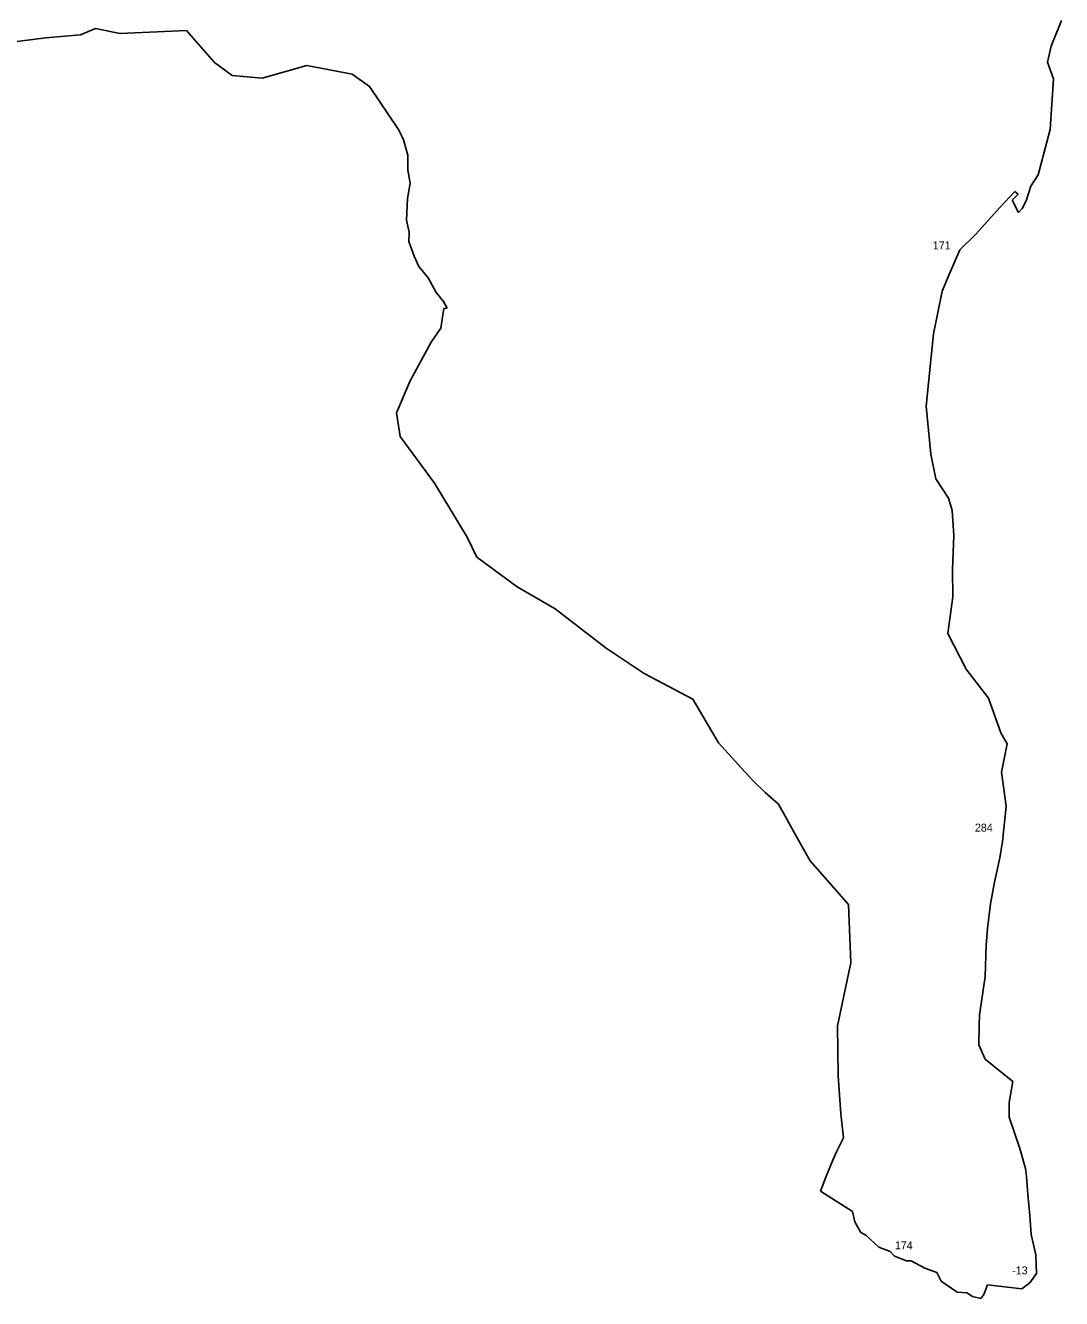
# Model space of a CAD drawing. Extents: x -787692 to -782531, y -972586 to -966265.
# Drawn here: x -783835 to -782540, y -972494 to -970904 of the extents above; entities that cross this region are included whole.
import ezdxf

# ---------------------------------------------------------------- set-up
doc = ezdxf.new("R2010")
doc.units = 0
for name, color, linetype in [('Vrstva 13', 7, 'Continuous'), ('Vrstva 15', 7, 'Continuous'), ('Vrstva 24', 7, 'Continuous')]:
    doc.layers.add(name, color=color, linetype=linetype)

msp = doc.modelspace()

# ---------------------------------------------------------------- linework, layer by layer
at = {"layer": 'Vrstva 13'}
for p, q in [((-782553.45, -970929.37), (-782540.43, -970897.48)), ((-783861.89, -970925.86), (-783809.33, -970919.07)), ((-783809.33, -970919.07), (-783785.71, -970917.04)), ((-783785.71, -970917.04), (-783766.14, -970915.34)), ((-783766.14, -970915.34), (-783747.3, -970907.33)), ((-783747.3, -970907.33), (-783716.72, -970913.63)), ((-783716.72, -970913.63), (-783633.91, -970909.95)), ((-783633.91, -970909.95), (-783598.87, -970949.9)), ((-782557.98, -970949.68), (-782553.45, -970929.37)), ((-783598.87, -970949.9), (-783576.71, -970966.08)), ((-783539.1, -970969.36), (-783483.29, -970953.82)), ((-783483.29, -970953.82), (-783426.92, -970964.66)), ((-782550.54, -970970.32), (-782557.98, -970949.68)), ((-783576.71, -970966.08), (-783539.1, -970969.36)), ((-783426.92, -970964.66), (-783405.08, -970979.79)), ((-783405.08, -970979.79), (-783368.9, -971033.49)), ((-782554.59, -971033.61), (-782550.54, -970970.32)), ((-783368.9, -971033.49), (-783364.33, -971042.87)), ((-783364.33, -971042.87), (-783362.75, -971046.47)), ((-783362.75, -971046.47), (-783358.91, -971059.7)), ((-782569.71, -971090.07), (-782554.59, -971033.61)), ((-783358.91, -971059.7), (-783357.13, -971065.79)), ((-783357.13, -971065.79), (-783357.25, -971084.54)), ((-783357.25, -971084.54), (-783354.38, -971100.62)), ((-782578.61, -971104.27), (-782569.71, -971090.07)), ((-783354.38, -971100.62), (-783357.53, -971119.96)), ((-782617.6, -971131.14), (-782598.68, -971111.07)), ((-782598.68, -971111.07), (-782594.47, -971114.47)), ((-782584.6, -971122.56), (-782578.61, -971104.27)), ((-783357.53, -971119.96), (-783358.66, -971147.06)), ((-782594.47, -971114.47), (-782601.99, -971121.83)), ((-782601.99, -971121.83), (-782594.23, -971137.13)), ((-782589.7, -971132.44), (-782584.6, -971122.56)), ((-782647.94, -971164.74), (-782617.6, -971131.14)), ((-782594.23, -971137.13), (-782589.7, -971132.44)), ((-783358.66, -971147.06), (-783355.55, -971161.93)), ((-783355.55, -971161.93), (-783355.72, -971173.38)), ((-783355.72, -971173.38), (-783349.44, -971191.91)), ((-782667.51, -971183.92), (-782647.94, -971164.74)), ((-783349.44, -971191.91), (-783343.62, -971204.77)), ((-782680.78, -971214.59), (-782667.51, -971183.92)), ((-783343.62, -971204.77), (-783331.69, -971219.06)), ((-783331.69, -971219.06), (-783321.98, -971237.43)), ((-782689.59, -971235.76), (-782680.78, -971214.59)), ((-783321.98, -971237.43), (-783312.68, -971248.43)), ((-782700.47, -971289.03), (-782689.59, -971235.76)), ((-783312.68, -971248.43), (-783307.86, -971256.99)), ((-783312.07, -971257.4), (-783315.95, -971281.83)), ((-783307.86, -971256.99), (-783312.07, -971257.4)), ((-783315.95, -971281.83), (-783327.92, -971299.23)), ((-783327.92, -971299.23), (-783354.21, -971347.74)), ((-782709.58, -971379.3), (-782700.47, -971289.03)), ((-783354.21, -971347.74), (-783371.52, -971387.51)), ((-782703.84, -971439.06), (-782709.58, -971379.3)), ((-783371.52, -971387.51), (-783366.78, -971417.02)), ((-783366.78, -971417.02), (-783323.72, -971475.54)), ((-782697.69, -971470.03), (-782703.84, -971439.06)), ((-783323.72, -971475.54), (-783283.13, -971542.75)), ((-782681.51, -971494.06), (-782697.69, -971470.03)), ((-782676.9, -971509.68), (-782681.51, -971494.06)), ((-782675.03, -971540.88), (-782676.9, -971509.68)), ((-782676.81, -971583.17), (-782675.03, -971540.88)), ((-783283.13, -971542.75), (-783271, -971567.75)), ((-783271, -971567.75), (-783220.45, -971604.89)), ((-782676.33, -971617.56), (-782676.81, -971583.17)), ((-783220.45, -971604.89), (-783173.21, -971632.24)), ((-782682.31, -971663.25), (-782676.33, -971617.56)), ((-783173.21, -971632.24), (-783109.39, -971681.68)), ((-782659.5, -971707.76), (-782682.31, -971663.25)), ((-783109.39, -971681.68), (-783062.07, -971713.08)), ((-783062.07, -971713.08), (-783001.16, -971745.2)), ((-782631.83, -971743.82), (-782659.5, -971707.76)), ((-783001.16, -971745.2), (-782968.89, -971799.58)), ((-782616.38, -971787.2), (-782631.83, -971743.82)), ((-782608.37, -971801.16), (-782616.38, -971787.2)), ((-782968.89, -971799.58), (-782940.5, -971830.89)), ((-782615.49, -971836.57), (-782608.37, -971801.16)), ((-782940.5, -971830.89), (-782925.69, -971847.23)), ((-782609.58, -971878.74), (-782615.49, -971836.57)), ((-782925.69, -971847.23), (-782910.65, -971861.8)), ((-782910.65, -971861.8), (-782893.9, -971876.53)), ((-782893.9, -971876.53), (-782868.51, -971922.29)), ((-782614.35, -971923.02), (-782609.58, -971878.74)), ((-782868.51, -971922.29), (-782854.59, -971947.37)), ((-782617.63, -971943.41), (-782614.35, -971923.02)), ((-782854.59, -971947.37), (-782806.42, -972001.74)), ((-782624.06, -971973.84), (-782617.63, -971943.41)), ((-782628.99, -972001.03), (-782624.06, -971973.84)), ((-782806.42, -972001.74), (-782803.49, -972074.68)), ((-782632.75, -972031.78), (-782628.99, -972001.03)), ((-782634.56, -972052.42), (-782632.75, -972031.78)), ((-782635.91, -972091.55), (-782634.56, -972052.42)), ((-782803.49, -972074.68), (-782820.16, -972153.43)), ((-782639.59, -972117.65), (-782635.91, -972091.55)), ((-782642.94, -972139.69), (-782639.59, -972117.65)), ((-782643.47, -972153.39), (-782642.94, -972139.69)), ((-782820.16, -972153.43), (-782819.35, -972215.95)), ((-782643.8, -972177.11), (-782643.47, -972153.39)), ((-782636, -972195.09), (-782643.8, -972177.11)), ((-782601.3, -972222.74), (-782636, -972195.09)), ((-782819.35, -972215.95), (-782816.29, -972263.21)), ((-782606.07, -972249.06), (-782601.3, -972222.74)), ((-782605.83, -972267.43), (-782606.07, -972249.06)), ((-782816.29, -972263.21), (-782812.89, -972293.13)), ((-782592.48, -972306.68), (-782605.83, -972267.43)), ((-782812.89, -972293.13), (-782821.78, -972310.61)), ((-782826.35, -972321.01), (-782834, -972340.42)), ((-782821.78, -972310.61), (-782826.35, -972321.01)), ((-782585.56, -972331.63), (-782592.48, -972306.68)), ((-782584.02, -972341.42), (-782585.56, -972331.63)), ((-782834, -972340.42), (-782841.6, -972359.92)), ((-782582.36, -972363.53), (-782584.02, -972341.42)), ((-782841.6, -972359.92), (-782801.72, -972385.41)), ((-782580.1, -972390.32), (-782582.36, -972363.53)), ((-782801.72, -972385.41), (-782798.56, -972398.27)), ((-782798.56, -972398.27), (-782791.12, -972411.38)), ((-782578.31, -972413.95), (-782580.1, -972390.32)), ((-782791.12, -972411.38), (-782784.81, -972414.72)), ((-782784.81, -972414.72), (-782768.55, -972429.73)), ((-782572.37, -972439.17), (-782578.31, -972413.95)), ((-782768.55, -972429.73), (-782754.48, -972435.03)), ((-782754.48, -972435.03), (-782749.19, -972440.89)), ((-782749.19, -972440.89), (-782734.34, -972446.8)), ((-782734.34, -972446.8), (-782728.16, -972446.84)), ((-782728.16, -972446.84), (-782711.29, -972455.86)), ((-782571.59, -972462.73), (-782572.37, -972439.17)), ((-782711.29, -972455.86), (-782696.12, -972461.36)), ((-782696.12, -972461.36), (-782690.83, -972472.32)), ((-782580.04, -972474.34), (-782571.59, -972462.73)), ((-782690.83, -972472.32), (-782670.68, -972486)), ((-782637.64, -972489.1), (-782632.95, -972476.68)), ((-782632.95, -972476.68), (-782590.07, -972481.82)), ((-782590.07, -972481.82), (-782580.04, -972474.34)), ((-782670.68, -972486), (-782658.92, -972486.96)), ((-782658.92, -972486.96), (-782651.64, -972491.33)), ((-782651.64, -972491.33), (-782641.28, -972493.96)), ((-782641.28, -972493.96), (-782637.64, -972489.1))]:
    msp.add_line(p, q, dxfattribs=at)

# ---------------------------------------------------------------- texts
at = {"layer": 'Vrstva 15'}
msp.add_text('-13', height=10, dxfattribs=at).set_placement((-782602.074, -972463.79))
at = {"layer": 'Vrstva 24'}
for s, p in [('171', (-782701.314, -971183.42)), ('284', (-782648.702, -971910.72)), ('174', (-782748.666, -972432.49))]:
    msp.add_text(s, height=10, dxfattribs=at).set_placement(p)

doc.saveas('drawing.dxf')
